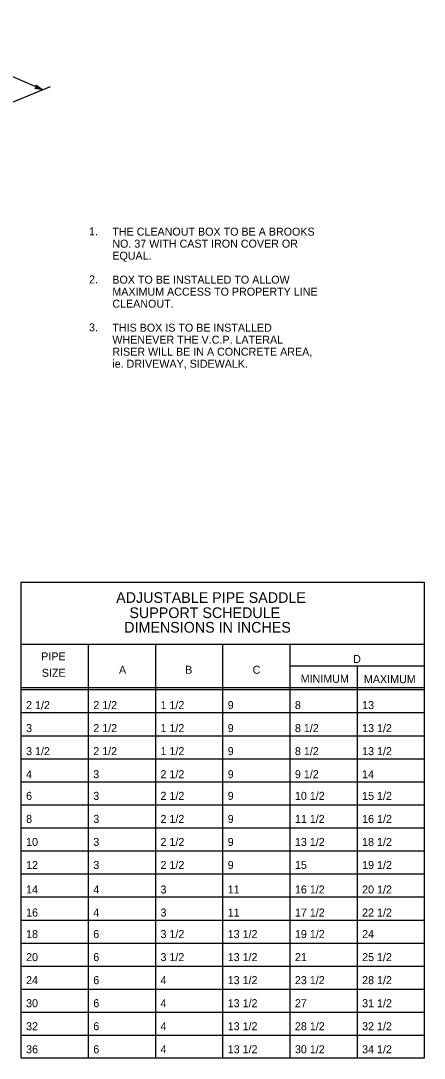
# Model space of a CAD drawing. Extents: x -121875 to -117742, y -103854 to -101122.
# Drawn here: x -120652 to -120350, y -102063 to -101286 of the extents above; entities that cross this region are included whole.
import ezdxf

# ---------------------------------------------------------------- set-up
doc = ezdxf.new("R2010")
doc.units = 0
for name, color, linetype in [('G-MARK', 7, 'Continuous'), ('G-TEXT', 7, 'Continuous'), ('Misc CnstDet(22)', 7, 'Continuous')]:
    doc.layers.add(name, color=color, linetype=linetype)

msp = doc.modelspace()

# ---------------------------------------------------------------- linework, layer by layer
at = {"layer": 'G-MARK'}
for p, q in [((-120635.78, -101337.49), (-120756.93, -101285.71)), ((-120630.31, -101335.26), (-120696.82, -101362.45))]:
    msp.add_line(p, q, dxfattribs=at)
at = {"layer": 'G-TEXT'}
for p, q in [((-120641.83, -101336.45), (-120640.59, -101335.52)), ((-120635.78, -101337.49), (-120641.83, -101336.45)), ((-120641.83, -101336.45), (-120641.83, -101336.45)), ((-120637.06, -101336.97), (-120641.48, -101336.2)), ((-120638.33, -101336.44), (-120641.18, -101335.95)), ((-120639.61, -101335.92), (-120640.83, -101335.71)), ((-120640.59, -101335.52), (-120640.82, -101333.98)), ((-120640.82, -101333.98), (-120640.82, -101333.98)), ((-120640.82, -101333.98), (-120635.78, -101337.49)), ((-120640.75, -101334.39), (-120637.05, -101336.97)), ((-120640.67, -101334.81), (-120638.33, -101336.44)), ((-120640.64, -101335.2), (-120639.61, -101335.92)), ((-120635.78, -101337.49), (-120635.78, -101337.49))]:
    msp.add_line(p, q, dxfattribs=at)
at = {"layer": 'Misc CnstDet(22)'}
for p, q in [((-120652.23, -101706.44), (-120350.14, -101706.44)), ((-120652.23, -102063.35), (-120652.23, -101706.44)), ((-120350.14, -101706.44), (-120350.14, -102063.35)), ((-120652.23, -101753.04), (-120350.14, -101753.04)), ((-120601.88, -101753.04), (-120601.88, -102063.35)), ((-120551.54, -101753.04), (-120551.54, -102063.35)), ((-120501.19, -101753.04), (-120501.19, -102063.35)), ((-120450.84, -101753.04), (-120450.84, -102063.35)), ((-120450.84, -101769.21), (-120350.14, -101769.21)), ((-120400.49, -101769.21), (-120400.49, -102063.35)), ((-120652.23, -101785.38), (-120350.14, -101785.38)), ((-120652.23, -101787.03), (-120350.14, -101787.03)), ((-120652.23, -101804.3), (-120350.14, -101804.3)), ((-120652.23, -101821.57), (-120350.14, -101821.57)), ((-120652.23, -101838.84), (-120350.14, -101838.84)), ((-120652.23, -101856.11), (-120350.14, -101856.11)), ((-120652.23, -101873.38), (-120350.14, -101873.38)), ((-120652.23, -101890.65), (-120350.14, -101890.65)), ((-120652.23, -101907.92), (-120350.14, -101907.92)), ((-120652.23, -101925.19), (-120350.14, -101925.19)), ((-120652.23, -101942.46), (-120350.14, -101942.46)), ((-120652.23, -101959.73), (-120350.14, -101959.73)), ((-120652.23, -101977), (-120350.14, -101977)), ((-120652.23, -101994.27), (-120350.14, -101994.27)), ((-120652.23, -102011.54), (-120350.14, -102011.54)), ((-120652.23, -102028.81), (-120350.14, -102028.81)), ((-120652.23, -102046.08), (-120350.14, -102046.08)), ((-120350.14, -102063.35), (-120652.23, -102063.35))]:
    msp.add_line(p, q, dxfattribs=at)

# ---------------------------------------------------------------- texts
for s, height, p in [('1.', 6, (-120601.28, -101446.56)), ('THE CLEANOUT BOX TO BE A BROOKS', 6, (-120583.84, -101446.78)), ('NO. 37 WITH CAST IRON COVER OR', 6, (-120583.84, -101455.78)), ('EQUAL.', 6, (-120583.84, -101464.78)), ('2.  ', 6, (-120601.28, -101482.56)), ('BOX TO BE INSTALLED TO ALLOW', 6, (-120583.84, -101482.78)), ('MAXIMUM ACCESS TO PROPERTY LINE', 6, (-120583.84, -101491.78)), ('CLEANOUT.', 6, (-120583.84, -101500.78)), ('3.', 6, (-120601.28, -101518.56)), ('THIS BOX IS TO BE INSTALLED', 6, (-120583.84, -101518.78)), ('WHENEVER THE V.C.P. LATERAL', 6, (-120583.84, -101527.78)), ('RISER WILL BE IN A CONCRETE AREA,', 6, (-120583.84, -101536.78)), ('ie. DRIVEWAY, SIDEWALK.', 6, (-120583.84, -101545.78)), ('ADJUSTABLE PIPE SADDLE', 8, (-120580.96, -101722.05)), ('SUPPORT SCHEDULE', 8, (-120571.03, -101733.43)), ('DIMENSIONS IN INCHES', 8, (-120574.92, -101744.34)), ('PIPE', 6, (-120637.13, -101765.13)), ('D', 6, (-120403.42, -101767.1)), ('SIZE', 6, (-120636.65, -101777.44)), ('A', 6, (-120578.86, -101775.18)), ('B', 6, (-120529.29, -101775.18)), ('C', 6, (-120478.72, -101775.18)), ('MINIMUM', 6, (-120442.7, -101781.93)), ('MAXIMUM', 6, (-120395.32, -101782.2)), ('2 1/2', 6, (-120648.44, -101801.64)), ('2 1/2', 6, (-120598.09, -101801.64)), ('1 1/2', 6, (-120547.74, -101801.64)), ('9', 6, (-120497.39, -101801.64)), ('8', 6, (-120447.03, -101801.64)), ('13', 6, (-120396.68, -101801.64)), ('3', 6, (-120648.44, -101818.9)), ('2 1/2', 6, (-120598.09, -101818.9)), ('1 1/2', 6, (-120547.74, -101818.9)), ('9', 6, (-120497.39, -101818.9)), ('8 1/2', 6, (-120447.03, -101818.9)), ('13 1/2', 6, (-120396.68, -101818.9)), ('3 1/2', 6, (-120648.44, -101836.17)), ('2 1/2', 6, (-120598.09, -101836.17)), ('1 1/2', 6, (-120547.74, -101836.17)), ('9', 6, (-120497.39, -101836.17)), ('8 1/2', 6, (-120447.03, -101836.17)), ('13 1/2', 6, (-120396.68, -101836.17)), ('4', 6, (-120648.44, -101853.44)), ('3', 6, (-120598.09, -101853.44)), ('2 1/2', 6, (-120547.74, -101853.44)), ('9', 6, (-120497.39, -101853.44)), ('9 1/2', 6, (-120447.03, -101853.44)), ('14', 6, (-120396.68, -101853.44)), ('6', 6, (-120648.44, -101869.67)), ('3', 6, (-120598.09, -101869.67)), ('2 1/2', 6, (-120547.74, -101869.67)), ('9', 6, (-120497.39, -101869.67)), ('10 1/2', 6, (-120447.03, -101869.67)), ('15 1/2', 6, (-120396.68, -101869.67)), ('8', 6, (-120648.44, -101886.94)), ('3', 6, (-120598.09, -101886.94)), ('2 1/2', 6, (-120547.74, -101886.94)), ('9', 6, (-120497.39, -101886.94)), ('11 1/2', 6, (-120447.03, -101886.94)), ('16 1/2', 6, (-120396.68, -101886.94)), ('10', 6, (-120648.44, -101904.21)), ('3', 6, (-120598.09, -101904.21)), ('2 1/2', 6, (-120547.74, -101904.21)), ('9', 6, (-120497.39, -101904.21)), ('13 1/2', 6, (-120447.03, -101904.21)), ('18 1/2', 6, (-120396.68, -101904.21)), ('12', 6, (-120648.44, -101921.47)), ('3', 6, (-120598.09, -101921.47)), ('2 1/2', 6, (-120547.74, -101921.47)), ('9', 6, (-120497.39, -101921.47)), ('15', 6, (-120447.03, -101921.47)), ('19 1/2', 6, (-120396.68, -101921.47)), ('14', 6, (-120648.44, -101939.85)), ('4', 6, (-120598.09, -101939.85)), ('3', 6, (-120547.74, -101939.85)), ('11', 6, (-120497.39, -101939.85)), ('16 1/2', 6, (-120447.03, -101939.85)), ('20 1/2', 6, (-120396.68, -101939.85)), ('16', 6, (-120648.44, -101957.11)), ('4', 6, (-120598.09, -101957.11)), ('3', 6, (-120547.74, -101957.11)), ('11', 6, (-120497.39, -101957.11)), ('17 1/2', 6, (-120447.03, -101957.11)), ('22 1/2', 6, (-120396.68, -101957.11)), ('18', 6, (-120648.44, -101973.28)), ('6', 6, (-120598.09, -101973.28)), ('3 1/2', 6, (-120547.74, -101973.28)), ('13 1/2', 6, (-120497.39, -101973.28)), ('19 1/2', 6, (-120447.03, -101973.28)), ('24', 6, (-120396.68, -101973.28)), ('20', 6, (-120648.44, -101990.54)), ('6', 6, (-120598.09, -101990.54)), ('3 1/2', 6, (-120547.74, -101990.54)), ('13 1/2', 6, (-120497.39, -101990.54)), ('21', 6, (-120447.03, -101990.54)), ('25 1/2', 6, (-120396.68, -101990.54)), ('24', 6, (-120648.44, -102007.81)), ('6', 6, (-120598.09, -102007.81)), ('4', 6, (-120547.74, -102007.81)), ('13 1/2', 6, (-120497.39, -102007.81)), ('23 1/2', 6, (-120447.03, -102007.81)), ('28 1/2', 6, (-120396.68, -102007.81)), ('30', 6, (-120648.44, -102025.08)), ('6', 6, (-120598.09, -102025.08)), ('4', 6, (-120547.74, -102025.08)), ('13 1/2', 6, (-120497.39, -102025.08)), ('27', 6, (-120447.03, -102025.08)), ('31 1/2', 6, (-120396.68, -102025.08)), ('32', 6, (-120648.44, -102042.35)), ('6', 6, (-120598.09, -102042.35)), ('4', 6, (-120547.74, -102042.35)), ('13 1/2', 6, (-120497.39, -102042.35)), ('28 1/2', 6, (-120447.03, -102042.35)), ('32 1/2', 6, (-120396.68, -102042.35)), ('36', 6, (-120648.44, -102059.62)), ('6', 6, (-120598.09, -102059.62)), ('4', 6, (-120547.74, -102059.62)), ('13 1/2', 6, (-120497.39, -102059.62)), ('30 1/2', 6, (-120447.03, -102059.62)), ('34 1/2', 6, (-120396.68, -102059.62))]:
    msp.add_text(s, height=height, dxfattribs=at).set_placement(p)

doc.saveas('drawing.dxf')
